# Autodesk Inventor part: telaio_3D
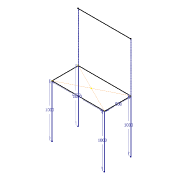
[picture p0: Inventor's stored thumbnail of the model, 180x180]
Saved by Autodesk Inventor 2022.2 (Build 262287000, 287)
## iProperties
Created: 2025-02
Part Number: telaio_3D
Material: Generico
Document SubType Name: Modeling
Designer: 18907419
Density: 1 g/cm^3
Appearance: Default
Author: 18907419
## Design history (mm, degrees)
sketch "Schizzo1"
  geometry: L1 (500, -250)-(-500, -250); L2 (-500, -250)-(-500, 250); L3 (-500, 250)-(500, 250); L4 (500, 250)-(500, -250); L5 (500, -250)-(-500, 250); L6 (-500, -250)-(500, 250); 1 further point
  constraints: 12 end point, 2 midpoint
  dimensions: "d9" = 1000 distance of L2.end L3.end; "d10" = 500 distance of L1.end L2.end
sketch "Schizzo 3D2" dims "d11" = 1000, "d12" = 1000, "d13" = 1000, "d14" = 1000
